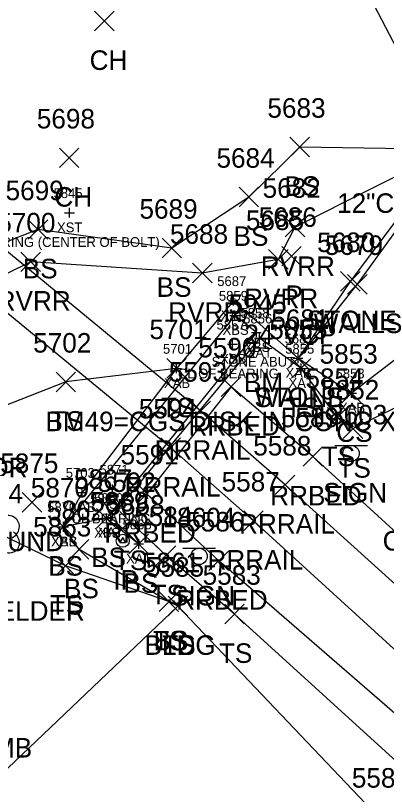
# Model space of a CAD drawing. Extents: x 1618146 to 1620418, y 640749 to 641927.
# Drawn here: x 1620082.5 to 1620120.5, y 641181.4 to 641261.1 of the extents above; entities that cross this region are included whole.
import ezdxf

# ---------------------------------------------------------------- set-up
doc = ezdxf.new("R2010")
doc.units = 0
for name, color, linetype in [('B_A', 7, 'Continuous'), ('B_C', 7, 'Continuous'), ('B_I', 7, 'Continuous'), ('B_TIC', 7, 'Continuous'), ('BSE', 7, 'Continuous'), ('BSUBM', 7, 'Continuous'), ('C_A', 7, 'Continuous'), ('C_C', 7, 'Continuous'), ('C_I', 7, 'Continuous'), ('CPBM', 7, 'Continuous'), ('D_A', 7, 'Continuous'), ('D_C', 7, 'Continuous'), ('D_I', 7, 'Continuous'), ('D_TIC', 7, 'Continuous'), ('L_A', 7, 'Continuous'), ('L_C', 7, 'Continuous'), ('L_I', 7, 'Continuous'), ('L_TIC', 7, 'Continuous'), ('LASF', 7, 'Continuous'), ('LAWE', 7, 'Continuous'), ('LBC', 7, 'Continuous'), ('LELB', 7, 'Continuous'), ('LTD', 7, 'Continuous'), ('LWS', 7, 'Continuous'), ('M_A', 7, 'Continuous'), ('M_I', 7, 'Continuous'), ('MPIR', 7, 'Continuous'), ('R_A', 7, 'Continuous'), ('R_I', 7, 'Continuous'), ('R_TIC', 7, 'Continuous'), ('RR', 7, 'Continuous'), ('RRB', 7, 'Continuous'), ('S_A', 7, 'Continuous'), ('S_I', 7, 'Continuous'), ('SSGN', 7, 'Continuous'), ('U_A', 7, 'Continuous')]:
    doc.layers.add(name, color=color, linetype=linetype)

msp = doc.modelspace()

# ---------------------------------------------------------------- linework, layer by layer
at = {"layer": 'B_TIC'}
for p, q in [((1620088.054, 641240.935), (1620088.13, 641240.935)), ((1620104.823, 641231.928), (1620104.899, 641231.928)), ((1620104.972, 641230.427), (1620105.047, 641230.427)), ((1620107.182, 641228.681), (1620107.258, 641228.681)), ((1620107.182, 641228.681), (1620107.258, 641228.681)), ((1620104.729, 641227.476), (1620104.804, 641227.476)), ((1620107.484, 641228.1), (1620107.56, 641228.1)), ((1620111.437, 641226.039), (1620111.512, 641226.039)), ((1620111.437, 641226.039), (1620111.512, 641226.039)), ((1620099.005, 641224.996), (1620099.08, 641224.996)), ((1620111.755, 641225.001), (1620111.831, 641225.001)), ((1620116.905, 641222.479), (1620116.981, 641222.479)), ((1620089.341, 641212.3), (1620089.417, 641212.3)), ((1620092.47, 641212.625), (1620092.545, 641212.625)), ((1620091.831, 641209.66), (1620091.906, 641209.66)), ((1620092.272, 641209.722), (1620092.347, 641209.722)), ((1620087.445, 641208.783), (1620087.52, 641208.783)), ((1620087.445, 641208.783), (1620087.52, 641208.783)), ((1620087.445, 641208.783), (1620087.52, 641208.783)), ((1620095.141, 641207.025), (1620095.217, 641207.025))]:
    msp.add_line(p, q, dxfattribs=at)
for points in [[(1620088.051, 641240.435), (1620088.051, 641241.435)], [(1620087.551, 641240.935), (1620088.551, 641240.935)], [(1620104.82, 641231.428), (1620104.82, 641232.428)], [(1620104.32, 641231.928), (1620105.32, 641231.928)], [(1620104.969, 641229.927), (1620104.969, 641230.927)], [(1620104.469, 641230.427), (1620105.469, 641230.427)], [(1620107.179, 641228.181), (1620107.179, 641229.181)], [(1620107.179, 641228.181), (1620107.179, 641229.181)], [(1620106.679, 641228.681), (1620107.679, 641228.681)], [(1620106.679, 641228.681), (1620107.679, 641228.681)], [(1620107.481, 641227.6), (1620107.481, 641228.6)], [(1620104.225, 641227.476), (1620105.225, 641227.476)], [(1620104.725, 641226.976), (1620104.725, 641227.976)], [(1620106.981, 641228.1), (1620107.981, 641228.1)], [(1620110.933, 641226.039), (1620111.933, 641226.039)], [(1620110.933, 641226.039), (1620111.933, 641226.039)], [(1620111.433, 641225.539), (1620111.433, 641226.539)], [(1620111.433, 641225.539), (1620111.433, 641226.539)], [(1620099.001, 641224.496), (1620099.001, 641225.496)], [(1620111.752, 641224.501), (1620111.752, 641225.501)], [(1620098.501, 641224.996), (1620099.501, 641224.996)], [(1620111.252, 641225.001), (1620112.252, 641225.001)], [(1620116.902, 641221.979), (1620116.902, 641222.979)], [(1620116.402, 641222.479), (1620117.402, 641222.479)], [(1620092.466, 641212.125), (1620092.466, 641213.125)], [(1620088.838, 641212.3), (1620089.838, 641212.3)], [(1620089.338, 641211.8), (1620089.338, 641212.8)], [(1620091.966, 641212.625), (1620092.966, 641212.625)], [(1620091.827, 641209.16), (1620091.827, 641210.16)], [(1620092.268, 641209.222), (1620092.268, 641210.222)], [(1620087.441, 641208.283), (1620087.441, 641209.283)], [(1620087.441, 641208.283), (1620087.441, 641209.283)], [(1620087.441, 641208.283), (1620087.441, 641209.283)], [(1620091.327, 641209.66), (1620092.327, 641209.66)], [(1620091.768, 641209.722), (1620092.768, 641209.722)], [(1620086.941, 641208.783), (1620087.941, 641208.783)], [(1620086.941, 641208.783), (1620087.941, 641208.783)], [(1620086.941, 641208.783), (1620087.941, 641208.783)], [(1620095.138, 641206.525), (1620095.138, 641207.525)], [(1620094.638, 641207.025), (1620095.638, 641207.025)]]:
    msp.add_lwpolyline(points, dxfattribs=at)
at = {"layer": 'BSE'}
for points in [[(1620107.179, 641228.681), (1620104.969, 641230.427), (1620087.441, 641208.783)], [(1620107.179, 641228.681), (1620091.827, 641209.66), (1620087.441, 641208.783)]]:
    msp.add_lwpolyline(points, dxfattribs=at)
at = {"layer": 'BSUBM'}
for points in [[(1620111.433, 641226.039), (1620104.82, 641231.928), (1620099.001, 641224.996), (1620089.338, 641212.3), (1620087.441, 641208.783)], [(1620111.752, 641225.001), (1620107.481, 641228.1), (1620092.268, 641209.722), (1620095.138, 641207.025)], [(1620111.433, 641226.039), (1620116.902, 641222.479)]]:
    msp.add_lwpolyline(points, dxfattribs=at)
at = {"layer": 'CPBM'}
for p, q in [((1620107.079, 641227.072), (1620107.079, 641228.072)), ((1620107.079, 641228.072), (1620108.079, 641228.072)), ((1620107.581, 641227.573), (1620107.581, 641227.573)), ((1620107.581, 641227.573), (1620107.581, 641227.573)), ((1620108.079, 641228.072), (1620108.079, 641227.072)), ((1620108.079, 641227.072), (1620107.079, 641227.072))]:
    msp.add_line(p, q, dxfattribs=at)
at = {"layer": 'D_TIC'}
for points in [[(1620109.767, 641235.485), (1620111.767, 641237.485)], [(1620111.767, 641235.485), (1620109.767, 641237.485)], [(1620083.224, 641210.289), (1620085.224, 641212.289)], [(1620085.224, 641210.289), (1620083.224, 641212.289)]]:
    msp.add_lwpolyline(points, dxfattribs=at)
at = {"layer": 'L_TIC'}
for points in [[(1620090.625, 641259.553), (1620092.625, 641261.553)], [(1620092.625, 641259.553), (1620090.625, 641261.553)], [(1620110.61, 641246.659), (1620112.61, 641248.659)], [(1620112.61, 641246.659), (1620110.61, 641248.659)], [(1620087.017, 641245.559), (1620089.017, 641247.559)], [(1620089.017, 641245.559), (1620087.017, 641247.559)], [(1620105.398, 641241.54), (1620107.398, 641243.54)], [(1620107.398, 641241.54), (1620105.398, 641243.54)], [(1620083.828, 641238.216), (1620085.828, 641240.216)], [(1620085.828, 641238.216), (1620083.828, 641240.216)], [(1620110.117, 641238.46), (1620112.117, 641240.46)], [(1620112.117, 641238.46), (1620110.117, 641240.46)], [(1620097.527, 641236.323), (1620099.527, 641238.323)], [(1620099.527, 641236.323), (1620097.527, 641238.323)], [(1620108.41, 641235.163), (1620110.41, 641237.163)], [(1620110.41, 641235.163), (1620108.41, 641237.163)], [(1620083.088, 641234.913), (1620085.088, 641236.913)], [(1620085.088, 641234.913), (1620083.088, 641236.913)], [(1620100.636, 641233.759), (1620102.636, 641235.759)], [(1620102.636, 641233.759), (1620100.636, 641235.759)], [(1620115.779, 641232.91), (1620117.779, 641234.91)], [(1620117.779, 641232.91), (1620115.779, 641234.91)], [(1620116.496, 641232.613), (1620118.496, 641234.613)], [(1620118.496, 641232.613), (1620116.496, 641234.613)], [(1620110.433, 641225.039), (1620112.433, 641227.039)], [(1620112.433, 641225.039), (1620110.433, 641227.039)], [(1620110.433, 641225.039), (1620112.433, 641227.039)], [(1620112.433, 641225.039), (1620110.433, 641227.039)], [(1620098.001, 641223.996), (1620100.001, 641225.996)], [(1620100.001, 641223.996), (1620098.001, 641225.996)], [(1620110.752, 641224.001), (1620112.752, 641226.001)], [(1620112.752, 641224.001), (1620110.752, 641226.001)], [(1620086.679, 641222.616), (1620088.679, 641224.616)], [(1620088.679, 641222.616), (1620086.679, 641224.616)], [(1620115.902, 641221.479), (1620117.902, 641223.479)], [(1620117.902, 641221.479), (1620115.902, 641223.479)], [(1620114.45, 641218.995), (1620116.45, 641220.995)], [(1620116.45, 641218.995), (1620114.45, 641220.995)], [(1620116.056, 641217.812), (1620118.056, 641219.812)], [(1620118.056, 641217.812), (1620116.056, 641219.812)], [(1620090.827, 641208.66), (1620092.827, 641210.66)], [(1620092.827, 641208.66), (1620090.827, 641210.66)], [(1620093.188, 641208.351), (1620095.188, 641210.351)], [(1620095.188, 641208.351), (1620093.188, 641210.351)], [(1620086.441, 641207.783), (1620088.441, 641209.783)], [(1620088.441, 641207.783), (1620086.441, 641209.783)], [(1620094.138, 641206.025), (1620096.138, 641208.025)], [(1620096.138, 641206.025), (1620094.138, 641208.025)], [(1620088.048, 641205.467), (1620090.048, 641207.467)], [(1620090.048, 641205.467), (1620088.048, 641207.467)], [(1620096.932, 641204.844), (1620098.932, 641206.844)], [(1620098.932, 641204.844), (1620096.932, 641206.844)], [(1620086.64, 641203.791), (1620088.64, 641205.791)], [(1620088.64, 641203.791), (1620086.64, 641205.791)], [(1620097.21, 641200.129), (1620099.21, 641202.129)], [(1620099.21, 641200.129), (1620097.21, 641202.129)], [(1620097.21, 641200.129), (1620099.21, 641202.129)], [(1620099.21, 641200.129), (1620097.21, 641202.129)], [(1620098.137, 641199.676), (1620100.137, 641201.676)], [(1620100.137, 641199.676), (1620098.137, 641201.676)], [(1620098.137, 641199.676), (1620100.137, 641201.676)], [(1620100.137, 641199.676), (1620098.137, 641201.676)], [(1620103.934, 641198.85), (1620105.934, 641200.85)], [(1620105.934, 641198.85), (1620103.934, 641200.85)]]:
    msp.add_lwpolyline(points, dxfattribs=at)
at = {"layer": 'LASF'}
msp.add_lwpolyline([(1620199.521, 641313.799), (1620179.367, 641298.383), (1620161.035, 641285.687), (1620141.172, 641269.891), (1620133.686, 641262.491), (1620132.653, 641253.954), (1620128.761, 641249.512), (1620128.684, 641249.148), (1620127.842, 641248.197), (1620126.924, 641247.392), (1620116.779, 641233.91), (1620111.433, 641226.039)], dxfattribs=at)
at = {"layer": 'LAWE'}
msp.add_lwpolyline([(1620126.924, 641247.392), (1620111.117, 641239.46), (1620109.41, 641236.163), (1620101.636, 641234.759), (1620084.088, 641235.913), (1620071.67, 641229.784), (1620042.737, 641224.388), (1620037.792, 641222.07), (1620025.57, 641215.03), (1620021.304, 641209.771), (1620016.061, 641211.085), (1620004.818, 641210.958), (1619989.454, 641201.04), (1619976.614, 641195.505), (1619948.377, 641191.059)], dxfattribs=at)
at = {"layer": 'LBC'}
msp.add_lwpolyline([(1620182.251, 641113.365), (1620138.873, 641158.876), (1620119.634, 641179.081), (1620099.137, 641200.676), (1620061.444, 641164.754), (1620044.431, 641182.84), (1620044.169, 641182.771), (1620022.603, 641162.294), (1620014.935, 641155.186), (1620024.72, 641144.878), (1620017.727, 641138.107), (1620002.991, 641123.903), (1620002.581, 641122.317), (1620005.727, 641115.216)], dxfattribs=at)
at = {"layer": 'LELB'}
for points in [[(1620094.279, 641315.291), (1620094.86, 641313.595), (1620100.39, 641301.82), (1620102.742, 641293.774), (1620108.781, 641281.996), (1620114.966, 641271.602), (1620116.112, 641268.122), (1620126.924, 641247.392)], [(1620126.924, 641247.392), (1620111.61, 641247.659), (1620106.398, 641242.54), (1620098.527, 641237.323), (1620084.828, 641239.216), (1620069.098, 641232.991), (1620064.278, 641237.198), (1620039.166, 641227.389), (1620035.445, 641222.864), (1620023.476, 641219.069), (1620012.158, 641216.975), (1620003.405, 641213.467), (1619988.117, 641206.058), (1619975.419, 641196.769), (1619947.495, 641194.474)], [(1620134.776, 641235.239), (1620133.025, 641230.264), (1620130.116, 641226.586), (1620123.352, 641221.964), (1620117.056, 641218.812), (1620115.45, 641219.995), (1620111.752, 641225.001)], [(1620133.025, 641230.264), (1620123.806, 641227.765), (1620116.902, 641222.479)], [(1620099.001, 641224.996), (1620087.679, 641223.616), (1620078.444, 641219.996), (1620048.672, 641217.648)], [(1620099.137, 641200.676), (1620098.21, 641201.129), (1620087.64, 641204.791), (1620080.66, 641208.17), (1620069.194, 641207.593), (1620063.849, 641208.645), (1620059.562, 641206.641), (1620048.927, 641206.852), (1620044.526, 641210.081), (1620039.577, 641216.282), (1620035.768, 641219.739)], [(1620091.827, 641209.66), (1620095.138, 641207.025)], [(1620198.161, 641096.651), (1620186.457, 641115.205), (1620172.223, 641131.175), (1620143.867, 641162.38), (1620123.748, 641182.705), (1620104.934, 641199.85), (1620097.932, 641205.844), (1620094.188, 641209.351)], [(1620098.21, 641201.129), (1620089.048, 641206.467), (1620087.441, 641208.783)]]:
    msp.add_lwpolyline(points, dxfattribs=at)
at = {"layer": 'LTD'}
for centre, major_axis, ratio in [((1620081.702, 641208.754), (-1.141, -0.483), 0.949671), ((1620081.66, 641207.337), (-1.09, 0.792), 0.841452)]:
    msp.add_ellipse(centre, major_axis=major_axis, ratio=ratio, start_param=1.570796, end_param=4.712389, dxfattribs=at)
at = {"layer": 'LWS'}
msp.add_lwpolyline([(1620138.412, 641259.674), (1620134.17, 641254.949), (1620126.214, 641245.687), (1620117.496, 641233.613), (1620111.433, 641226.039)], dxfattribs=at)
at = {"layer": 'MPIR'}
msp.add_lwpolyline([(1620093.496, 641207.682), (1620093.207, 641207.182), (1620093.784, 641207.182)], close=True, dxfattribs=at)
msp.add_circle((1620093.496, 641207.349), 0.667, dxfattribs=at)
at = {"layer": 'R_TIC'}
for points in [[(1620103.578, 641222.126), (1620105.578, 641224.126)], [(1620105.578, 641222.126), (1620103.578, 641224.126)], [(1620100.472, 641219.641), (1620102.472, 641221.641)], [(1620102.472, 641219.641), (1620100.472, 641221.641)], [(1620097.404, 641215.876), (1620099.404, 641217.876)], [(1620099.404, 641215.876), (1620097.404, 641217.876)], [(1620111.946, 641214.974), (1620113.946, 641216.974)], [(1620113.946, 641214.974), (1620111.946, 641216.974)], [(1620109.111, 641212.081), (1620111.111, 641214.081)], [(1620111.111, 641212.081), (1620109.111, 641214.081)], [(1620094.968, 641211.166), (1620096.968, 641213.166)], [(1620096.968, 641211.166), (1620094.968, 641213.166)], [(1620094.968, 641211.166), (1620096.968, 641213.166)], [(1620096.968, 641211.166), (1620094.968, 641213.166)], [(1620105.878, 641208.401), (1620107.878, 641210.401)], [(1620107.878, 641208.401), (1620105.878, 641210.401)], [(1620102.318, 641204.304), (1620104.318, 641206.304)], [(1620104.318, 641204.304), (1620102.318, 641206.304)]]:
    msp.add_lwpolyline(points, dxfattribs=at)
at = {"layer": 'RR'}
for points in [[(1620192.149, 641127.788), (1620168.312, 641155.994), (1620153.359, 641171.838), (1620133.437, 641191.994), (1620110.111, 641213.081), (1620101.472, 641220.641), (1620055.356, 641258.678), (1620021.942, 641286.099), (1619984.199, 641317.184), (1619946.809, 641347.804), (1619927.299, 641363.881), (1619890.892, 641393.618), (1619862.546, 641416.891)], [(1620190.752, 641121.585), (1620164.758, 641152.663), (1620149.827, 641168.387), (1620129.761, 641188.505), (1620106.878, 641209.401), (1620098.404, 641216.876), (1620053.4, 641253.963), (1620018.83, 641282.236), (1619980.557, 641313.635), (1619944.224, 641343.671), (1619924.209, 641360.052), (1619888.22, 641389.605), (1619859.159, 641413.425)]]:
    msp.add_lwpolyline(points, dxfattribs=at)
at = {"layer": 'RRB'}
for points in [[(1620282.833, 641005.905), (1620262.956, 641036.105), (1620245.554, 641062.879), (1620222.8, 641095.958), (1620205.802, 641118.707), (1620193.459, 641134.423), (1620171.398, 641158.878), (1620156.473, 641175.88), (1620136.028, 641194.899), (1620112.946, 641215.974), (1620104.578, 641223.126), (1620095.968, 641212.166)], [(1620271.861, 640991.557), (1620248.91, 641026.87), (1620231.317, 641051.296), (1620208.546, 641087.677), (1620199.84, 641100.892), (1620189.043, 641115.525), (1620174.379, 641133.159), (1620146.778, 641165.447), (1620126.451, 641185.248), (1620103.318, 641205.304), (1620095.968, 641212.166)]]:
    msp.add_lwpolyline(points, dxfattribs=at)
at = {"layer": 'SSGN'}
for p, q in [((1620115.215, 641217.121), (1620118.548, 641217.121)), ((1620116.862, 641216.288), (1620116.862, 641216.288)), ((1620099.661, 641206.587), (1620102.994, 641206.587)), ((1620101.307, 641205.753), (1620101.307, 641205.753))]:
    msp.add_line(p, q, dxfattribs=at)
for centre in [(1620116.862, 641216.288), (1620101.307, 641205.753)]:
    msp.add_circle(centre, 0.833, dxfattribs=at)

# ---------------------------------------------------------------- texts
at = {"layer": 'B_A'}
for s, p in [('XST', (1620086.771, 641238.935)), ('XAB', (1620103.54, 641229.928)), ('XBS', (1620103.709, 641228.427)), ('XBS', (1620105.919, 641226.681)), ('XBS', (1620105.919, 641226.681)), ('XAT', (1620106.186, 641226.1)), ('XSB', (1620103.462, 641225.476)), ('XAB', (1620110.154, 641224.039)), ('XAB', (1620110.154, 641224.039)), ('XAB', (1620097.722, 641222.996)), ('XAT', (1620110.457, 641223.001)), ('XAB', (1620115.622, 641220.479)), ('XSB', (1620091.202, 641210.625)), ('XAB', (1620088.058, 641210.3)), ('XBS', (1620090.567, 641207.66)), ('XAT', (1620090.973, 641207.722)), ('XAB', (1620086.162, 641206.783)), ('XBS', (1620086.182, 641206.783)), ('XBS', (1620086.182, 641206.783)), ('XAT', (1620093.842, 641205.025))]:
    msp.add_text(s, height=1, dxfattribs=at).set_placement(p)
at = {"layer": 'B_C'}
for s, p in [('CL BEARING (CENTER OF BOLT)', (1620076.334, 641237.435)), ('STONE ABUT', (1620102.592, 641225.181)), ('STONE ABUT', (1620102.592, 641225.181)), ('CL OF BEARING', (1620099.139, 641223.976)), ('CL BEARING', (1620088.265, 641209.125))]:
    msp.add_text(s, height=1, dxfattribs=at).set_placement(p)
at = {"layer": 'B_I'}
for s, p in [('5845', (1620086.421, 641242.435)), ('5687', (1620103.166, 641233.428)), ('5859', (1620103.335, 641231.927)), ('5858', (1620105.549, 641230.181)), ('5858', (1620105.549, 641230.181)), ('5856', (1620105.823, 641229.6)), ('5857', (1620103.095, 641228.976)), ('5681', (1620110.063, 641227.539)), ('5681', (1620110.063, 641227.539)), ('5701', (1620097.615, 641226.496)), ('5855', (1620110.122, 641226.501)), ('5853', (1620115.272, 641223.979)), ('5703', (1620087.668, 641213.8)), ('5871', (1620091.12, 641214.125)), ('5867', (1620090.174, 641211.16)), ('5860', (1620090.571, 641211.222)), ('5870', (1620085.768, 641210.283)), ('5870', (1620085.768, 641210.283)), ('5870', (1620085.768, 641210.283)), ('5868', (1620093.484, 641208.525))]:
    msp.add_text(s, height=1, dxfattribs=at).set_placement(p)
at = {"layer": 'C_A'}
msp.add_text('BM', height=2, dxfattribs=at).set_placement((1620105.896, 641222.573))
at = {"layer": 'C_C'}
msp.add_text('BM49=CGS DISK IN CONC XAT', height=2, dxfattribs=at).set_placement((1620085.59, 641218.573))
at = {"layer": 'C_I'}
msp.add_text('5945', height=2, dxfattribs=at).set_placement((1620104.322, 641230.573))
at = {"layer": 'D_A'}
for s, p in [('P', (1620110.145, 641231.485)), ('UND', (1620081.696, 641206.289))]:
    msp.add_text(s, height=2, dxfattribs=at).set_placement(p)
at = {"layer": 'D_C'}
for s, p in [('12"CIP OUTLET', (1620115.429, 641240.918)), ('24"VCP', (1620105.94, 641227.485)), ('9"CGMP POOR', (1620064.674, 641213.847))]:
    msp.add_text(s, height=2, dxfattribs=at).set_placement(p)
at = {"layer": 'D_I'}
for s, p in [('5686', (1620107.405, 641239.485)), ('5875', (1620080.964, 641214.289))]:
    msp.add_text(s, height=2, dxfattribs=at).set_placement(p)
at = {"layer": 'L_A'}
for s, p in [('CH', (1620090.113, 641255.553)), ('BS', (1620110.05, 641242.659)), ('CH', (1620086.505, 641241.559)), ('BS', (1620104.839, 641237.54)), ('BS', (1620083.269, 641234.216)), ('RVRR', (1620107.629, 641234.46)), ('BS', (1620096.968, 641232.323)), ('RVRR', (1620105.922, 641231.163)), ('RVRR', (1620080.6, 641230.913)), ('RVRR', (1620098.148, 641229.759)), ('STONE', (1620112.322, 641228.91)), ('WALLS', (1620113.04, 641228.613)), ('WALLS', (1620106.977, 641221.039)), ('STONE', (1620106.977, 641221.039)), ('TS', (1620097.411, 641219.996)), ('TS', (1620110.161, 641220.001)), ('TS', (1620086.088, 641218.616)), ('CS', (1620115.343, 641217.479)), ('TS', (1620113.86, 641214.995)), ('TS', (1620115.466, 641213.812)), ('CONCPAD', (1620120.094, 641206.351)), ('BS', (1620090.268, 641204.66)), ('TS', (1620092.597, 641204.351)), ('BS', (1620085.882, 641203.783)), ('BS', (1620087.489, 641201.467)), ('BS', (1620093.579, 641202.025)), ('TS', (1620096.342, 641200.844)), ('TS', (1620086.05, 641199.791)), ('TS', (1620096.62, 641196.129)), ('BS', (1620096.651, 641196.129)), ('BLDG', (1620095.728, 641195.676)), ('TS', (1620097.547, 641195.676)), ('TS', (1620103.343, 641194.85))]:
    msp.add_text(s, height=2, dxfattribs=at).set_placement(p)
at = {"layer": 'L_C'}
msp.add_text('3-S.BOX ELDER', height=2, dxfattribs=at).set_placement((1620069.408, 641199.17))
at = {"layer": 'L_I'}
for s, p in [('5683', (1620108.302, 641250.659)), ('5698', (1620084.71, 641249.559)), ('5684', (1620103.091, 641245.54)), ('5699', (1620081.514, 641242.216)), ('5682', (1620107.81, 641242.46)), ('5689', (1620095.212, 641240.323)), ('5685', (1620106.103, 641239.163)), ('5700', (1620080.663, 641238.913)), ('5688', (1620098.329, 641237.759)), ('5680', (1620113.385, 641236.91)), ('5679', (1620114.181, 641236.613)), ('5681', (1620108.693, 641229.039)), ('5681', (1620108.693, 641229.039)), ('5701', (1620096.23, 641227.996)), ('5855', (1620108.492, 641228.001)), ('5702', (1620084.34, 641226.616)), ('5853', (1620113.642, 641225.479)), ('5854', (1620112.19, 641222.995)), ('5852', (1620113.796, 641221.812)), ('5867', (1620088.52, 641212.66)), ('5592', (1620090.928, 641212.351)), ('5864', (1620077.353, 641211.17)), ('5864', (1620077.353, 641211.17)), ('5870', (1620084.095, 641211.783)), ('5862', (1620085.741, 641209.467)), ('5868', (1620091.831, 641210.025)), ('5584', (1620094.673, 641208.844)), ('5863', (1620084.333, 641207.791)), ('5861', (1620095.47, 641204.129)), ('5861', (1620095.47, 641204.129)), ('5585', (1620095.877, 641203.676)), ('5585', (1620095.877, 641203.676)), ('5583', (1620101.674, 641202.85)), ('5581', (1620116.941, 641182.081))]:
    msp.add_text(s, height=2, dxfattribs=at).set_placement(p)
at = {"layer": 'M_A'}
msp.add_text('IP', height=2, dxfattribs=at).set_placement((1620092.543, 641202.349))
at = {"layer": 'M_I'}
msp.add_text('5869', height=2, dxfattribs=at).set_placement((1620090.181, 641210.349))
at = {"layer": 'R_A'}
for s, p in [('RRBED', (1620100.224, 641218.126)), ('RRRAIL', (1620096.764, 641215.641)), ('RRRAIL', (1620093.695, 641211.876)), ('RRBED', (1620108.591, 641210.974)), ('RRRAIL', (1620105.403, 641208.081)), ('RRBED', (1620091.613, 641207.166)), ('RRBED', (1620091.613, 641207.166)), ('RRRAIL', (1620102.17, 641204.401)), ('RRBED', (1620098.964, 641200.304))]:
    msp.add_text(s, height=2, dxfattribs=at).set_placement(p)
at = {"layer": 'R_I'}
for s, p in [('5590', (1620101.232, 641226.126)), ('5593', (1620098.213, 641223.641)), ('5594', (1620095.144, 641219.876)), ('5589', (1620109.678, 641218.974)), ('5588', (1620106.852, 641216.081)), ('5591', (1620093.275, 641215.166)), ('5591', (1620093.275, 641215.166)), ('5587', (1620103.618, 641212.401)), ('5586', (1620100.003, 641208.304))]:
    msp.add_text(s, height=2, dxfattribs=at).set_placement(p)
at = {"layer": 'S_A'}
for p in [(1620114, 641211.268), (1620098.445, 641200.733)]:
    msp.add_text('SIGN', height=2, dxfattribs=at).set_placement(p)
at = {"layer": 'S_I'}
for s, p in [('18603', (1620113.126, 641219.268)), ('18604', (1620097.572, 641208.733))]:
    msp.add_text(s, height=2, dxfattribs=at).set_placement(p)
at = {"layer": 'U_A'}
msp.add_text('COMB', height=2, dxfattribs=at).set_placement((1620076.211, 641185.166))

doc.saveas('drawing.dxf')
